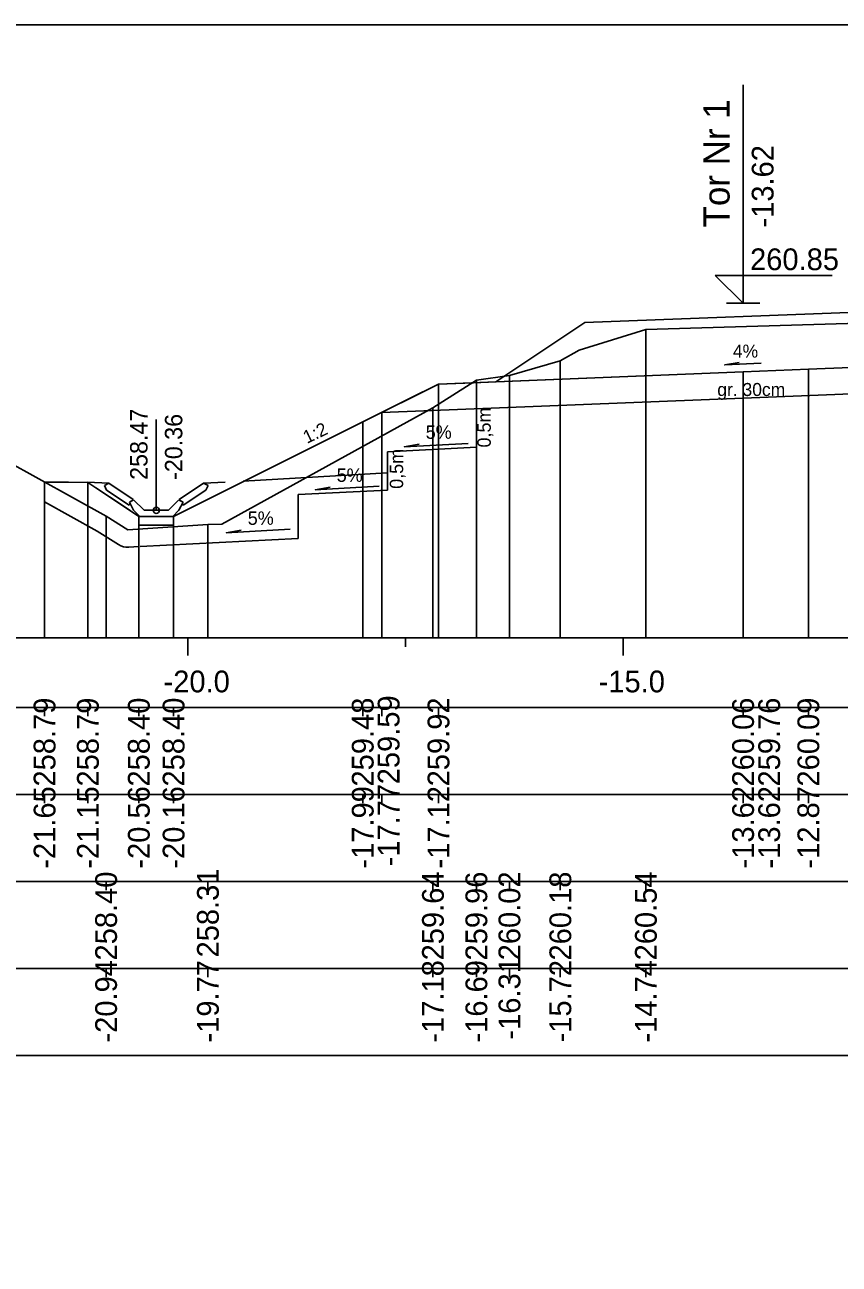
# Model space of a CAD drawing. Extents: x 6516023 to 6560129, y 5513077 to 5529206.
# Drawn here: x 6517288.34 to 6517297.7, y 5514498.91 to 5514513.16 of the extents above; entities that cross this region are included whole.
import ezdxf

# ---------------------------------------------------------------- set-up
doc = ezdxf.new("R2010")
doc.units = 0
for name, color, linetype in [('IR_default', 7, 'Continuous'), ('TOR_PRZEK_P-komponent', 7, 'Continuous'), ('TOR_PRZEK_P-odwodnienie', 7, 'Continuous'), ('TOR_PRZEK_P-opisy', 7, 'Continuous'), ('TOR_PRZEK_P-schodkowanie+wymiana', 7, 'Continuous'), ('TOR_PRZEK_P-tabelka istniejace', 7, 'Continuous'), ('TOR_PRZEK_P-tabelka projektowane', 7, 'Continuous'), ('TOR_PRZEK_P-teren istniejacy', 7, 'Continuous'), ('TOR_PRZEK_P-tory projektowane', 7, 'Continuous'), ('TOR_PRZEK_P-uklad odniesienia', 7, 'Continuous'), ('TOR_PRZEK_P-warstwa ochronna I', 7, 'Continuous'), ('TOR_PRZEK_P-warstwa ochronna II', 7, 'Continuous'), ('TOR_PS_T-skarpy projektowane', 7, 'Continuous'), ('TOR_RAMKI-ramka+tabelka 1', 7, 'Continuous')]:
    doc.layers.add(name, color=color, linetype=linetype)

msp = doc.modelspace()

# ---------------------------------------------------------------- linework, layer by layer
at = {"layer": 'IR_default'}
msp.add_lwpolyline([(6517288.564, 5514507.899), (6517288.842, 5514507.896), (6517289.063, 5514507.894), (6517289.118, 5514507.857), (6517289.153, 5514507.834), (6517289.455, 5514507.633), (6517289.648, 5514507.504), (6517289.892, 5514507.504), (6517290.048, 5514507.504), (6517291.372, 5514508.166), (6517292.222, 5514508.59), (6517292.222, 5514508.59), (6517292.222, 5514508.59), (6517292.752, 5514508.856), (6517293.092, 5514509.025), (6517293.493, 5514509.041), (6517293.75, 5514509.052), (6517294.416, 5514509.495), (6517294.775, 5514509.735), (6517298.211, 5514509.865)], dxfattribs=at)
at = {"layer": 'TOR_PRZEK_P-komponent'}
msp.add_lwpolyline([(6517294.775, 5514509.735), (6517298.211, 5514509.865), (6517299.146, 5514509.242), (6517302.945, 5514509.118), (6517303.963, 5514509.797), (6517307.463, 5514509.798), (6517308.463, 5514509.798), (6517311.963, 5514509.798), (6517312.513, 5514509.799), (6517316.013, 5514509.799), (6517317.359, 5514508.902), (6517313.513, 5514509.056), (6517310.213, 5514509.188), (6517309.463, 5514509.218), (6517308.263, 5514509.266), (6517307.663, 5514509.266), (6517306.463, 5514509.218), (6517305.713, 5514509.188), (6517303.513, 5514509.1), (6517298.792, 5514509.253), (6517297.342, 5514509.195), (6517296.592, 5514509.165), (6517293.75, 5514509.052)], close=True, dxfattribs=at)
at = {"layer": 'TOR_PRZEK_P-odwodnienie'}
for p, q in [((6517289.848, 5514507.574), (6517289.848, 5514508.618)), ((6517289.539, 5514507.633), (6517289.278, 5514507.807)), ((6517289.584, 5514507.699), (6517289.303, 5514507.886)), ((6517290.113, 5514507.699), (6517290.393, 5514507.886)), ((6517290.157, 5514507.633), (6517290.419, 5514507.807)), ((6517289.55, 5514507.65), (6517289.539, 5514507.633)), ((6517289.541, 5514507.669), (6517289.588, 5514507.693)), ((6517289.584, 5514507.699), (6517289.575, 5514507.687)), ((6517289.708, 5514507.574), (6517289.588, 5514507.693)), ((6517289.988, 5514507.574), (6517290.108, 5514507.693)), ((6517290.108, 5514507.693), (6517290.156, 5514507.669)), ((6517290.113, 5514507.699), (6517290.121, 5514507.687)), ((6517290.146, 5514507.65), (6517290.157, 5514507.633)), ((6517289.658, 5514507.504), (6517290.038, 5514507.504)), ((6517289.708, 5514507.574), (6517289.988, 5514507.574))]:
    msp.add_line(p, q, dxfattribs=at)
for points in [[(6517289.057, 5514507.898), (6517289.303, 5514507.886)], [(6517290.64, 5514507.898), (6517290.393, 5514507.886)], [(6517289.253, 5514507.86), (6517289.303, 5514507.886)], [(6517289.253, 5514507.86), (6517289.278, 5514507.807)], [(6517290.444, 5514507.86), (6517290.393, 5514507.886)], [(6517290.444, 5514507.86), (6517290.419, 5514507.807)], [(6517289.575, 5514507.687), (6517289.54, 5514507.668)], [(6517289.54, 5514507.668), (6517289.55, 5514507.65)], [(6517289.588, 5514507.574), (6517289.541, 5514507.669)], [(6517290.108, 5514507.574), (6517290.156, 5514507.669)], [(6517290.121, 5514507.687), (6517290.157, 5514507.668)], [(6517290.157, 5514507.668), (6517290.146, 5514507.65)], [(6517289.658, 5514507.504), (6517289.588, 5514507.574)], [(6517289.648, 5514507.504), (6517289.648, 5514507.504), (6517289.648, 5514507.504), (6517289.648, 5514507.503), (6517289.648, 5514507.504), (6517289.649, 5514507.503), (6517289.648, 5514507.504), (6517289.649, 5514507.504)], [(6517289.648, 5514507.504), (6517289.648, 5514507.504), (6517289.648, 5514507.504), (6517289.648, 5514507.503), (6517289.648, 5514507.504), (6517289.649, 5514507.503), (6517289.648, 5514507.504), (6517289.649, 5514507.504)], [(6517290.048, 5514507.504), (6517289.648, 5514507.504), (6517289.648, 5514507.404), (6517290.048, 5514507.404), (6517290.048, 5514507.504)], [(6517290.038, 5514507.504), (6517290.108, 5514507.574)], [(6517290.048, 5514507.504), (6517290.048, 5514507.504), (6517290.048, 5514507.504), (6517290.048, 5514507.503), (6517290.048, 5514507.504), (6517290.049, 5514507.503), (6517290.048, 5514507.504), (6517290.049, 5514507.504)], [(6517290.048, 5514507.504), (6517290.048, 5514507.504), (6517290.048, 5514507.504), (6517290.048, 5514507.503), (6517290.048, 5514507.504), (6517290.049, 5514507.503), (6517290.048, 5514507.504), (6517290.049, 5514507.504)]]:
    msp.add_lwpolyline(points, dxfattribs=at)
msp.add_circle((6517289.848, 5514507.574), 0.035, dxfattribs=at)
at = {"layer": 'TOR_PRZEK_P-opisy'}
msp.add_lwpolyline([(6517296.798, 5514509.264), (6517296.381, 5514509.245), (6517296.548, 5514509.273)], dxfattribs=at)
at = {"layer": 'TOR_PRZEK_P-schodkowanie+wymiana'}
for p, q in [((6517293.527, 5514508.743), (6517293.527, 5514508.3)), ((6517293.527, 5514508.3), (6517292.504, 5514508.248)), ((6517292.504, 5514508.248), (6517292.504, 5514507.805)), ((6517292.504, 5514508.006), (6517290.847, 5514507.908)), ((6517292.504, 5514507.805), (6517291.481, 5514507.754)), ((6517291.481, 5514507.754), (6517291.481, 5514507.249)), ((6517291.481, 5514507.249), (6517289.665, 5514507.158))]:
    msp.add_line(p, q, dxfattribs=at)
at = {"layer": 'TOR_PRZEK_P-tabelka istniejace'}
for p, q in [((6517289.272, 5514503.206), (6517289.272, 5514503.306)), ((6517290.442, 5514503.206), (6517290.442, 5514503.306)), ((6517293.028, 5514503.206), (6517293.028, 5514503.306)), ((6517293.527, 5514503.206), (6517293.527, 5514503.306)), ((6517293.907, 5514503.206), (6517293.907, 5514503.306)), ((6517294.492, 5514503.206), (6517294.492, 5514503.306)), ((6517295.475, 5514503.206), (6517295.475, 5514503.306)), ((6517269.163, 5514502.306), (6517352.963, 5514502.306)), ((6517289.272, 5514502.206), (6517289.272, 5514502.306)), ((6517290.442, 5514502.206), (6517290.442, 5514502.306)), ((6517293.028, 5514502.206), (6517293.028, 5514502.306)), ((6517293.527, 5514502.206), (6517293.527, 5514502.306)), ((6517293.907, 5514502.206), (6517293.907, 5514502.306)), ((6517294.492, 5514502.206), (6517294.492, 5514502.306)), ((6517295.475, 5514502.206), (6517295.475, 5514502.306))]:
    msp.add_line(p, q, dxfattribs=at)
for points in [[(6517295.475, 5514509.651), (6517295.475, 5514506.306), (6517295.475, 5514506.176), (6517295.475, 5514506.106)], [(6517294.492, 5514509.291), (6517294.492, 5514506.306), (6517294.492, 5514506.176), (6517294.492, 5514506.106)], [(6517293.527, 5514509.071), (6517293.527, 5514506.306), (6517293.527, 5514506.176), (6517293.527, 5514506.106)], [(6517293.907, 5514509.124), (6517293.907, 5514506.306), (6517293.907, 5514506.176), (6517293.907, 5514506.106)], [(6517293.028, 5514508.751), (6517293.028, 5514506.306), (6517293.028, 5514506.176), (6517293.028, 5514506.106)], [(6517289.272, 5514507.508), (6517289.272, 5514506.306), (6517289.272, 5514506.176), (6517289.272, 5514506.106)], [(6517290.442, 5514507.412), (6517290.442, 5514506.306), (6517290.442, 5514506.176), (6517290.442, 5514506.106)]]:
    msp.add_lwpolyline(points, dxfattribs=at)
msp.add_lwpolyline([(6517269.163, 5514503.306), (6517269.163, 5514501.306), (6517352.963, 5514501.306), (6517352.963, 5514503.306)], close=True, dxfattribs=at)
at = {"layer": 'TOR_PRZEK_P-tabelka projektowane'}
for p, q in [((6517288.565, 5514505.206), (6517288.565, 5514505.306)), ((6517289.063, 5514505.206), (6517289.063, 5514505.306)), ((6517289.648, 5514505.206), (6517289.648, 5514505.306)), ((6517290.048, 5514505.206), (6517290.048, 5514505.306)), ((6517292.221, 5514505.206), (6517292.221, 5514505.306)), ((6517292.439, 5514505.206), (6517292.439, 5514505.306)), ((6517293.092, 5514505.206), (6517293.092, 5514505.306)), ((6517296.592, 5514505.206), (6517296.592, 5514505.306)), ((6517296.592, 5514505.206), (6517296.592, 5514505.306)), ((6517297.342, 5514505.206), (6517297.342, 5514505.306)), ((6517269.163, 5514504.306), (6517352.963, 5514504.306)), ((6517288.565, 5514504.206), (6517288.565, 5514504.306)), ((6517289.063, 5514504.206), (6517289.063, 5514504.306)), ((6517289.648, 5514504.206), (6517289.648, 5514504.306)), ((6517290.048, 5514504.206), (6517290.048, 5514504.306)), ((6517292.221, 5514504.206), (6517292.221, 5514504.306)), ((6517292.439, 5514504.206), (6517292.439, 5514504.306)), ((6517293.092, 5514504.206), (6517293.092, 5514504.306)), ((6517296.592, 5514504.206), (6517296.592, 5514504.306)), ((6517296.592, 5514504.206), (6517296.592, 5514504.306)), ((6517297.342, 5514504.206), (6517297.342, 5514504.306))]:
    msp.add_line(p, q, dxfattribs=at)
for points in [[(6517297.342, 5514509.195), (6517297.342, 5514506.306), (6517297.342, 5514506.176), (6517297.342, 5514506.106)], [(6517296.592, 5514509.165), (6517296.592, 5514506.306), (6517296.592, 5514506.176), (6517296.592, 5514506.106)], [(6517293.092, 5514509.025), (6517293.092, 5514506.306), (6517293.092, 5514506.176), (6517293.092, 5514506.106)], [(6517296.592, 5514508.865), (6517296.592, 5514506.306), (6517296.592, 5514506.176), (6517296.592, 5514506.106)], [(6517292.439, 5514508.699), (6517292.439, 5514506.306), (6517292.439, 5514506.176), (6517292.439, 5514506.106)], [(6517292.221, 5514508.59), (6517292.221, 5514506.306), (6517292.221, 5514506.176), (6517292.221, 5514506.106)], [(6517288.565, 5514507.899), (6517288.565, 5514506.306), (6517288.565, 5514506.176), (6517288.565, 5514506.106)], [(6517289.063, 5514507.894), (6517289.063, 5514506.306), (6517289.063, 5514506.176), (6517289.063, 5514506.106)], [(6517289.648, 5514507.504), (6517289.648, 5514506.306), (6517289.648, 5514506.176), (6517289.648, 5514506.106)], [(6517290.048, 5514507.504), (6517290.048, 5514506.306), (6517290.048, 5514506.176), (6517290.048, 5514506.106)]]:
    msp.add_lwpolyline(points, dxfattribs=at)
msp.add_lwpolyline([(6517269.163, 5514505.306), (6517269.163, 5514503.306), (6517352.963, 5514503.306), (6517352.963, 5514505.306)], close=True, dxfattribs=at)
at = {"layer": 'TOR_PRZEK_P-teren istniejacy'}
msp.add_lwpolyline([(6517288.112, 5514508.149), (6517289.272, 5514507.508), (6517289.521, 5514507.349), (6517290.442, 5514507.412), (6517290.603, 5514507.413), (6517293.028, 5514508.751), (6517293.527, 5514509.071), (6517293.907, 5514509.124), (6517294.492, 5514509.291), (6517294.71, 5514509.417), (6517295.475, 5514509.651), (6517298.048, 5514509.731), (6517298.759, 5514509.735), (6517299.186, 5514509.556), (6517299.433, 5514509.45), (6517299.692, 5514509.457), (6517303.875, 5514509.236), (6517304.091, 5514509.37), (6517304.934, 5514509.835), (6517307.495, 5514509.771)], dxfattribs=at)
at = {"layer": 'TOR_PRZEK_P-tory projektowane'}
for p, q in [((6517296.592, 5514510.833), (6517296.592, 5514512.465)), ((6517296.592, 5514510.833), (6517296.592, 5514509.955)), ((6517296.592, 5514509.955), (6517296.273, 5514510.274)), ((6517296.273, 5514510.274), (6517297.617, 5514510.274)), ((6517296.4, 5514509.955), (6517296.783, 5514509.955))]:
    msp.add_line(p, q, dxfattribs=at)
at = {"layer": 'TOR_PRZEK_P-uklad odniesienia'}
for p, q in [((6517272.963, 5514506.106), (6517352.963, 5514506.106)), ((6517290.213, 5514505.906), (6517290.213, 5514506.106)), ((6517292.713, 5514506.006), (6517292.713, 5514506.106)), ((6517295.213, 5514505.906), (6517295.213, 5514506.106))]:
    msp.add_line(p, q, dxfattribs=at)
at = {"layer": 'TOR_PRZEK_P-warstwa ochronna I'}
msp.add_lwpolyline([(6517292.439, 5514508.699), (6517296.592, 5514508.865), (6517298.792, 5514508.953), (6517303.264, 5514508.808)], dxfattribs=at)
at = {"layer": 'TOR_PRZEK_P-warstwa ochronna II'}
msp.add_lwpolyline([(6517288.565, 5514507.899), (6517289.063, 5514507.894), (6517289.648, 5514507.504), (6517290.048, 5514507.504), (6517292.221, 5514508.59), (6517292.222, 5514508.59), (6517293.092, 5514509.025), (6517296.592, 5514509.165), (6517297.342, 5514509.195), (6517298.791, 5514509.253), (6517303.513, 5514509.1), (6517305.713, 5514509.188), (6517306.463, 5514509.218), (6517307.663, 5514509.266)], dxfattribs=at)
at = {"layer": 'TOR_PS_T-skarpy projektowane'}
for points in [[(6517293.434, 5514508.344), (6517292.698, 5514508.304), (6517292.871, 5514508.335)], [(6517292.411, 5514507.85), (6517291.676, 5514507.81), (6517291.848, 5514507.841)], [(6517288.565, 5514507.67), (6517289.17, 5514507.336), (6517289.413, 5514507.181)], [(6517291.388, 5514507.356), (6517290.653, 5514507.316), (6517290.825, 5514507.347)], [(6517289.534, 5514507.15), (6517289.648, 5514507.158)]]:
    msp.add_lwpolyline(points, dxfattribs=at)
msp.add_arc((6517289.521, 5514507.349), 0.2, 237.558, 273.8898, dxfattribs=at)
at = {"layer": 'TOR_RAMKI-ramka+tabelka 1'}
msp.add_lwpolyline([(6517179.513, 5514513.156), (6517427.013, 5514513.156), (6517427.013, 5514484.656), (6517179.513, 5514484.656)], close=True, dxfattribs=at)

# ---------------------------------------------------------------- texts
at = {"layer": 'TOR_PRZEK_P-odwodnienie'}
for s, p in [('258.47', (6517289.748, 5514507.924)), ('-20.36', (6517290.148, 5514507.924))]:
    msp.add_text(s, height=0.2, rotation=90, dxfattribs=at).set_placement(p)
at = {"layer": 'TOR_PRZEK_P-opisy'}
for s, rotation, p in [('4%', 0.1515, (6517296.475, 5514509.329)), ('1:2', 25.4204, (6517291.58, 5514508.337))]:
    msp.add_text(s, height=0.15, rotation=rotation, dxfattribs=at).set_placement(p)
at = {"layer": 'TOR_PRZEK_P-schodkowanie+wymiana'}
for p in [(6517293.693, 5514508.296), (6517292.686, 5514507.821)]:
    msp.add_text('0,5m', height=0.1545, rotation=90, dxfattribs=at).set_placement(p)
at = {"layer": 'TOR_PRZEK_P-tabelka istniejace'}
for s, p in [('258.40', (6517289.397, 5514502.398)), ('258.31', (6517290.567, 5514502.433)), ('259.64', (6517293.153, 5514502.399)), ('259.96', (6517293.652, 5514502.398)), ('260.02', (6517294.032, 5514502.4)), ('260.18', (6517294.617, 5514502.398)), ('260.54', (6517295.6, 5514502.399)), ('-20.94', (6517289.397, 5514501.455)), ('-19.77', (6517290.567, 5514501.455)), ('-17.18', (6517293.153, 5514501.454)), ('-16.69', (6517293.652, 5514501.455)), ('-16.31', (6517294.032, 5514501.489)), ('-15.72', (6517294.617, 5514501.456)), ('-14.74', (6517295.6, 5514501.455))]:
    msp.add_text(s, height=0.25, rotation=90, dxfattribs=at).set_placement(p)
at = {"layer": 'TOR_PRZEK_P-tabelka projektowane'}
for s, p in [('258.79', (6517288.69, 5514504.398)), ('258.79', (6517289.188, 5514504.398)), ('258.40', (6517289.773, 5514504.398)), ('258.40', (6517290.173, 5514504.398)), ('259.48', (6517292.346, 5514504.398)), ('259.59', (6517292.644, 5514504.424)), ('259.92', (6517293.217, 5514504.4)), ('260.06', (6517296.717, 5514504.398)), ('259.76', (6517297.017, 5514504.398)), ('260.09', (6517297.467, 5514504.398)), ('-21.65', (6517288.69, 5514503.453)), ('-21.15', (6517289.188, 5514503.453)), ('-20.56', (6517289.773, 5514503.454)), ('-20.16', (6517290.173, 5514503.454)), ('-17.99', (6517292.346, 5514503.455)), ('-17.77', (6517292.644, 5514503.48)), ('-17.12', (6517293.217, 5514503.456)), ('-13.62', (6517296.717, 5514503.456)), ('-13.62', (6517297.017, 5514503.456)), ('-12.87', (6517297.467, 5514503.455))]:
    msp.add_text(s, height=0.25, rotation=90, dxfattribs=at).set_placement(p)
at = {"layer": 'TOR_PRZEK_P-tory projektowane'}
for s, height, p in [('Tor Nr 1', 0.3, (6517296.437, 5514510.827)), ('-13.62', 0.25, (6517296.942, 5514510.825))]:
    msp.add_text(s, height=height, rotation=90, dxfattribs=at).set_placement(p)
msp.add_text('260.85', height=0.25, dxfattribs=at).set_placement((6517296.672, 5514510.335))
at = {"layer": 'TOR_PRZEK_P-uklad odniesienia'}
for s, p in [('-20.0', (6517289.932, 5514505.481)), ('-15.0', (6517294.932, 5514505.481))]:
    msp.add_text(s, height=0.25, dxfattribs=at).set_placement(p)
at = {"layer": 'TOR_PRZEK_P-warstwa ochronna I'}
msp.add_text('gr. 30cm', height=0.15, dxfattribs=at).set_placement((6517296.296, 5514508.888))
at = {"layer": 'TOR_PS_T-skarpy projektowane'}
for p in [(6517292.945, 5514508.396), (6517291.922, 5514507.901), (6517290.9, 5514507.407)]:
    msp.add_text('5%', height=0.1545, dxfattribs=at).set_placement(p)

doc.saveas('drawing.dxf')
